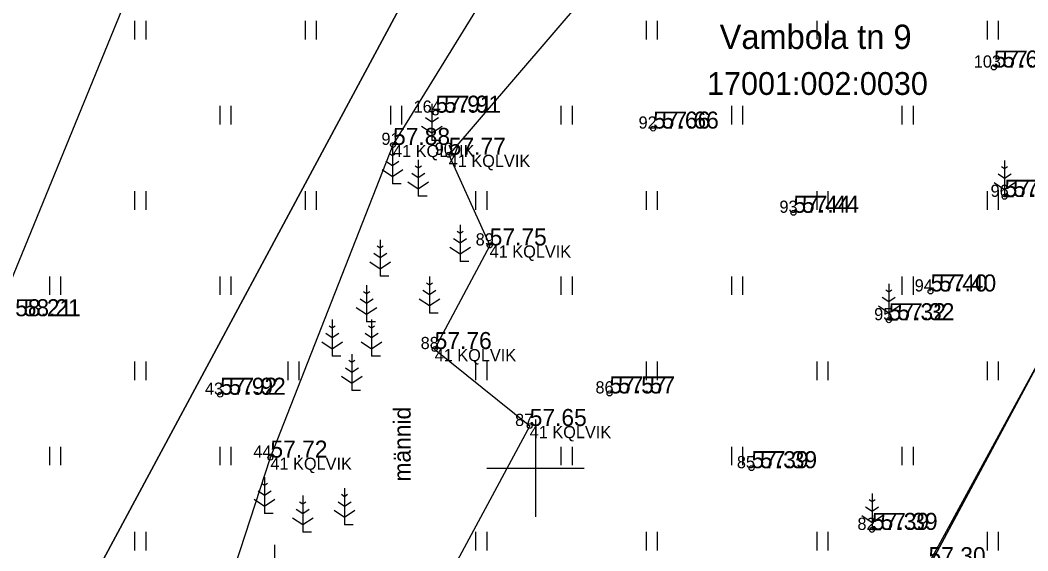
# Model space of a CAD drawing. Extents: x 640891 to 641083, y 6456526 to 6456669.
# Drawn here: x 640928.85 to 640970.21, y 6456596.6 to 6456618.41 of the extents above; entities that cross this region are included whole.
import ezdxf

# ---------------------------------------------------------------- set-up
doc = ezdxf.new("R2010")
doc.units = 0
for name, color, linetype in [('100koma2', 7, 'Continuous'), ('HALJASTUS', 7, 'Continuous'), ('KORGUS', 7, 'Continuous'), ('MOOTKORG', 7, 'Continuous'), ('MOOTMPUNKT', 7, 'Continuous'), ('MOOTNR', 7, 'Continuous'), ('MOOTPIIR', 7, 'Continuous'), ('PIIR', 7, 'Continuous'), ('PUU', 7, 'Continuous'), ('VORK', 7, 'Continuous')]:
    doc.layers.add(name, color=color, linetype=linetype)

msp = doc.modelspace()

# ---------------------------------------------------------------- linework, layer by layer
at = {"layer": 'HALJASTUS'}
for p, q in [((640933.545, 6456618.381), (640933.545, 6456617.619)), ((640934, 6456618.381), (640934, 6456617.619)), ((640940.545, 6456618.381), (640940.545, 6456617.619)), ((640941, 6456618.381), (640941, 6456617.619)), ((640954.545, 6456618.381), (640954.545, 6456617.619)), ((640955, 6456618.381), (640955, 6456617.619)), ((640961.545, 6456618.381), (640961.545, 6456617.619)), ((640962, 6456618.381), (640962, 6456617.619)), ((640968.545, 6456618.381), (640968.545, 6456617.619)), ((640969, 6456618.381), (640969, 6456617.619)), ((640937.045, 6456614.881), (640937.045, 6456614.119)), ((640937.5, 6456614.881), (640937.5, 6456614.119)), ((640944.045, 6456614.881), (640944.045, 6456614.119)), ((640944.5, 6456614.881), (640944.5, 6456614.119)), ((640951.045, 6456614.881), (640951.045, 6456614.119)), ((640951.5, 6456614.881), (640951.5, 6456614.119)), ((640958.045, 6456614.881), (640958.045, 6456614.119)), ((640958.5, 6456614.881), (640958.5, 6456614.119)), ((640965.045, 6456614.881), (640965.045, 6456614.119)), ((640965.5, 6456614.881), (640965.5, 6456614.119)), ((640933.545, 6456611.381), (640933.545, 6456610.619)), ((640934, 6456611.381), (640934, 6456610.619)), ((640940.545, 6456611.381), (640940.545, 6456610.619)), ((640941, 6456611.381), (640941, 6456610.619)), ((640947.545, 6456611.381), (640947.545, 6456610.619)), ((640948, 6456611.381), (640948, 6456610.619)), ((640954.545, 6456611.381), (640954.545, 6456610.619)), ((640955, 6456611.381), (640955, 6456610.619)), ((640961.545, 6456611.381), (640961.545, 6456610.619)), ((640962, 6456611.381), (640962, 6456610.619)), ((640968.545, 6456611.381), (640968.545, 6456610.619)), ((640969, 6456611.381), (640969, 6456610.619)), ((640930.045, 6456607.881), (640930.045, 6456607.119)), ((640930.5, 6456607.881), (640930.5, 6456607.119)), ((640937.045, 6456607.881), (640937.045, 6456607.119)), ((640937.5, 6456607.881), (640937.5, 6456607.119)), ((640951.045, 6456607.881), (640951.045, 6456607.119)), ((640951.5, 6456607.881), (640951.5, 6456607.119)), ((640958.045, 6456607.881), (640958.045, 6456607.119)), ((640958.5, 6456607.881), (640958.5, 6456607.119)), ((640965.045, 6456607.881), (640965.045, 6456607.119)), ((640965.5, 6456607.881), (640965.5, 6456607.119)), ((640933.545, 6456604.381), (640933.545, 6456603.619)), ((640934, 6456604.381), (640934, 6456603.619)), ((640939.828, 6456604.381), (640939.828, 6456603.619)), ((640940.283, 6456604.381), (640940.283, 6456603.619)), ((640947.545, 6456604.381), (640947.545, 6456603.619)), ((640948, 6456604.381), (640948, 6456603.619)), ((640954.545, 6456604.381), (640954.545, 6456603.619)), ((640955, 6456604.381), (640955, 6456603.619)), ((640961.545, 6456604.381), (640961.545, 6456603.619)), ((640962, 6456604.381), (640962, 6456603.619)), ((640968.545, 6456604.381), (640968.545, 6456603.619)), ((640969, 6456604.381), (640969, 6456603.619)), ((640930.045, 6456600.881), (640930.045, 6456600.119)), ((640930.5, 6456600.881), (640930.5, 6456600.119)), ((640937.045, 6456600.881), (640937.045, 6456600.119)), ((640937.5, 6456600.881), (640937.5, 6456600.119)), ((640951.045, 6456600.881), (640951.045, 6456600.119)), ((640951.5, 6456600.881), (640951.5, 6456600.119)), ((640958.045, 6456600.881), (640958.045, 6456600.119)), ((640958.5, 6456600.881), (640958.5, 6456600.119)), ((640965.045, 6456600.881), (640965.045, 6456600.119)), ((640965.5, 6456600.881), (640965.5, 6456600.119)), ((640933.545, 6456597.381), (640933.545, 6456596.619)), ((640934, 6456597.381), (640934, 6456596.619)), ((640947.545, 6456597.381), (640947.545, 6456596.619)), ((640948, 6456597.381), (640948, 6456596.619)), ((640954.545, 6456597.381), (640954.545, 6456596.619)), ((640955, 6456597.381), (640955, 6456596.619)), ((640961.545, 6456597.381), (640961.545, 6456596.619)), ((640962, 6456597.381), (640962, 6456596.619)), ((640968.545, 6456597.381), (640968.545, 6456596.619)), ((640969, 6456597.381), (640969, 6456596.619))]:
    msp.add_line(p, q, dxfattribs=at)
for points in [[(640940.859, 6456588.363), (640936.098, 6456589.959), (640937.267, 6456594.734), (640939.119, 6456600.434), (640944.153, 6456613.282), (640950.33, 6456623.315), (640954.177, 6456630.888), (640962.196, 6456639.436), (640963.998, 6456638.677), (640968.745, 6456632.01), (640966.503, 6456625.352), (640963.655, 6456626.075), (640962.794, 6456629.058), (640958.598, 6456629.914), (640954.818, 6456622.648), (640946.439, 6456612.875), (640948.12, 6456609.151), (640945.862, 6456604.895), (640949.763, 6456601.734), (640945.05, 6456592.964), (640940.483, 6456588.68)], [(640962.925, 6456576.62), (640957.383, 6456579.521), (640966.138, 6456596.056), (640972.417, 6456607.592), (640977.059, 6456616.501), (640985.041, 6456631.518)]]:
    msp.add_lwpolyline(points, dxfattribs=at)
at = {"layer": 'KORGUS'}
for centre in [(640968.818, 6456616.461), (640945.896, 6456614.606), (640954.833, 6456613.952), (640969.258, 6456611.148), (640960.591, 6456610.493), (640966.219, 6456607.261), (640964.504, 6456606.079), (640937.057, 6456603.018), (640953.038, 6456603.072), (640958.868, 6456600), (640963.817, 6456597.465)]:
    msp.add_circle(centre, 0.1, dxfattribs=at)
at = {"layer": 'MOOTMPUNKT'}
for centre in [(640968.818, 6456616.461), (640945.896, 6456614.606), (640954.833, 6456613.952), (640944.153, 6456613.282), (640946.439, 6456612.875), (640969.258, 6456611.148), (640960.591, 6456610.493), (640948.12, 6456609.151), (640966.219, 6456607.261), (640964.504, 6456606.079), (640945.862, 6456604.895), (640937.057, 6456603.018), (640953.038, 6456603.072), (640949.763, 6456601.734), (640939.119, 6456600.434), (640958.868, 6456600), (640963.817, 6456597.465)]:
    msp.add_circle(centre, 0.1, dxfattribs=at)
at = {"layer": 'MOOTPIIR'}
msp.add_lwpolyline([(640976.662, 6456538.007), (640959.29, 6456546.142), (640961.328, 6456555.553), (640965.053, 6456562.959), (640957.364, 6456564.816), (640935.712, 6456572.952), (640933.007, 6456573.069), (640928.881, 6456566.092), (640925.582, 6456561.827), (640921.958, 6456562.765), (640911.417, 6456572.885), (640912.029, 6456574.013), (640921.076, 6456588.216), (640912.945, 6456593.7), (640910.627, 6456595.318), (640915.929, 6456603.505), (640924.706, 6456598.502), (640938.233, 6456631.58)], dxfattribs=at)
at = {"layer": 'PIIR'}
for points in [[(640930.79, 6456593.51), (640904.36, 6456607.7), (640935.64, 6456665.95), (640960.76, 6456649.34)], [(640957.22, 6456579.32), (640930.79, 6456593.51), (640960.76, 6456649.34), (640985.89, 6456632.73)], [(640983.63, 6456565.13), (640957.22, 6456579.32), (640985.89, 6456632.73), (641000.58, 6456623), (641011.01, 6456616.1)]]:
    msp.add_lwpolyline(points, close=True, dxfattribs=at)
at = {"layer": 'PUU'}
for p, q in [((640945.749, 6456614.969), (640945.749, 6456613.469)), ((640945.749, 6456614.219), (640945.483, 6456614.397)), ((640945.749, 6456614.619), (640945.625, 6456614.702)), ((640945.874, 6456614.702), (640945.749, 6456614.619)), ((640946.016, 6456614.397), (640945.749, 6456614.219)), ((640945.325, 6456614.058), (640945.749, 6456613.775)), ((640945.749, 6456613.775), (640946.173, 6456614.058)), ((640944.131, 6456613.178), (640944.131, 6456611.678)), ((640946.109, 6456613.469), (640945.749, 6456613.469)), ((640944.131, 6456612.828), (640944.006, 6456612.911)), ((640944.255, 6456612.911), (640944.131, 6456612.828)), ((640944.131, 6456612.428), (640943.864, 6456612.606)), ((640944.397, 6456612.606), (640944.131, 6456612.428)), ((640945.191, 6456612.323), (640945.067, 6456612.406)), ((640945.191, 6456612.673), (640945.191, 6456611.173)), ((640945.316, 6456612.406), (640945.191, 6456612.323)), ((640969.258, 6456612.298), (640969.134, 6456612.381)), ((640969.258, 6456612.648), (640969.258, 6456611.148)), ((640969.383, 6456612.381), (640969.258, 6456612.298)), ((640943.706, 6456612.268), (640944.131, 6456611.985)), ((640944.131, 6456611.985), (640944.555, 6456612.268)), ((640945.191, 6456611.923), (640944.924, 6456612.101)), ((640945.458, 6456612.101), (640945.191, 6456611.923)), ((640969.258, 6456611.898), (640968.992, 6456612.076)), ((640969.525, 6456612.076), (640969.258, 6456611.898)), ((640944.491, 6456611.678), (640944.131, 6456611.678)), ((640944.767, 6456611.762), (640945.191, 6456611.479)), ((640945.191, 6456611.479), (640945.615, 6456611.762)), ((640968.834, 6456611.737), (640969.258, 6456611.454)), ((640969.258, 6456611.454), (640969.683, 6456611.737)), ((640945.551, 6456611.173), (640945.191, 6456611.173)), ((640969.618, 6456611.148), (640969.258, 6456611.148)), ((640946.908, 6456609.995), (640946.908, 6456608.495)), ((640946.908, 6456609.245), (640946.642, 6456609.422)), ((640946.908, 6456609.645), (640946.784, 6456609.728)), ((640947.033, 6456609.728), (640946.908, 6456609.645)), ((640947.175, 6456609.422), (640946.908, 6456609.245)), ((640943.626, 6456609.038), (640943.501, 6456609.121)), ((640943.626, 6456609.388), (640943.626, 6456607.888)), ((640943.75, 6456609.121), (640943.626, 6456609.038)), ((640946.484, 6456609.084), (640946.908, 6456608.801)), ((640946.908, 6456608.801), (640947.332, 6456609.084)), ((640943.626, 6456608.638), (640943.359, 6456608.816)), ((640943.892, 6456608.816), (640943.626, 6456608.638)), ((640943.201, 6456608.478), (640943.626, 6456608.195)), ((640943.626, 6456608.195), (640944.05, 6456608.478)), ((640947.268, 6456608.495), (640946.908, 6456608.495)), ((640943.986, 6456607.888), (640943.626, 6456607.888)), ((640945.646, 6456607.872), (640945.646, 6456606.372)), ((640943.07, 6456607.518), (640943.07, 6456606.018)), ((640945.646, 6456607.522), (640945.521, 6456607.605)), ((640945.77, 6456607.605), (640945.646, 6456607.522)), ((640964.504, 6456607.579), (640964.504, 6456606.079)), ((640943.07, 6456606.768), (640942.803, 6456606.946)), ((640943.07, 6456607.168), (640942.946, 6456607.251)), ((640943.194, 6456607.251), (640943.07, 6456607.168)), ((640943.337, 6456606.946), (640943.07, 6456606.768)), ((640945.221, 6456606.961), (640945.646, 6456606.679)), ((640945.646, 6456607.122), (640945.379, 6456607.3)), ((640945.912, 6456607.3), (640945.646, 6456607.122)), ((640945.646, 6456606.679), (640946.07, 6456606.961)), ((640964.504, 6456606.829), (640964.237, 6456607.007)), ((640964.504, 6456607.229), (640964.379, 6456607.312)), ((640964.628, 6456607.312), (640964.504, 6456607.229)), ((640964.77, 6456607.007), (640964.504, 6456606.829)), ((640942.646, 6456606.608), (640943.07, 6456606.325)), ((640943.07, 6456606.325), (640943.494, 6456606.608)), ((640964.08, 6456606.669), (640964.504, 6456606.386)), ((640964.504, 6456606.386), (640964.928, 6456606.669)), ((640941.656, 6456606.103), (640941.656, 6456604.603)), ((640943.272, 6456606.103), (640943.272, 6456604.603)), ((640946.006, 6456606.372), (640945.646, 6456606.372)), ((640941.656, 6456605.753), (640941.532, 6456605.836)), ((640941.78, 6456605.836), (640941.656, 6456605.753)), ((640943.43, 6456606.018), (640943.07, 6456606.018)), ((640943.272, 6456605.753), (640943.148, 6456605.836)), ((640943.396, 6456605.836), (640943.272, 6456605.753)), ((640964.864, 6456606.079), (640964.504, 6456606.079)), ((640941.656, 6456605.353), (640941.389, 6456605.531)), ((640941.923, 6456605.531), (640941.656, 6456605.353)), ((640943.272, 6456605.353), (640943.005, 6456605.531)), ((640943.539, 6456605.531), (640943.272, 6456605.353)), ((640941.232, 6456605.193), (640941.656, 6456604.91)), ((640941.656, 6456604.91), (640942.08, 6456605.193)), ((640942.848, 6456605.193), (640943.272, 6456604.91)), ((640943.272, 6456604.91), (640943.696, 6456605.193)), ((640942.016, 6456604.603), (640941.656, 6456604.603)), ((640942.464, 6456604.688), (640942.464, 6456603.188)), ((640943.632, 6456604.603), (640943.272, 6456604.603)), ((640942.464, 6456603.938), (640942.197, 6456604.116)), ((640942.464, 6456604.338), (640942.34, 6456604.421)), ((640942.588, 6456604.421), (640942.464, 6456604.338)), ((640942.731, 6456604.116), (640942.464, 6456603.938)), ((640942.04, 6456603.778), (640942.464, 6456603.495)), ((640942.464, 6456603.495), (640942.888, 6456603.778)), ((640942.824, 6456603.188), (640942.464, 6456603.188)), ((640938.878, 6456599.635), (640938.878, 6456598.135)), ((640938.878, 6456598.885), (640938.612, 6456599.063)), ((640938.878, 6456599.285), (640938.754, 6456599.368)), ((640939.003, 6456599.368), (640938.878, 6456599.285)), ((640939.145, 6456599.063), (640938.878, 6456598.885)), ((640942.161, 6456599.18), (640942.161, 6456597.68)), ((640938.454, 6456598.724), (640938.878, 6456598.442)), ((640938.878, 6456598.442), (640939.303, 6456598.724)), ((640940.444, 6456598.877), (640940.444, 6456597.377)), ((640942.161, 6456598.83), (640942.037, 6456598.913)), ((640942.285, 6456598.913), (640942.161, 6456598.83)), ((640963.817, 6456598.615), (640963.693, 6456598.698)), ((640963.817, 6456598.965), (640963.817, 6456597.465)), ((640963.942, 6456598.698), (640963.817, 6456598.615)), ((640940.444, 6456598.127), (640940.177, 6456598.305)), ((640940.444, 6456598.527), (640940.32, 6456598.61)), ((640940.568, 6456598.61), (640940.444, 6456598.527)), ((640940.711, 6456598.305), (640940.444, 6456598.127)), ((640941.737, 6456598.27), (640942.161, 6456597.987)), ((640942.161, 6456598.43), (640941.894, 6456598.608)), ((640942.428, 6456598.608), (640942.161, 6456598.43)), ((640942.161, 6456597.987), (640942.585, 6456598.27)), ((640963.817, 6456598.215), (640963.551, 6456598.393)), ((640964.084, 6456598.393), (640963.817, 6456598.215)), ((640939.238, 6456598.135), (640938.878, 6456598.135)), ((640940.02, 6456597.966), (640940.444, 6456597.684)), ((640940.444, 6456597.684), (640940.868, 6456597.966)), ((640963.393, 6456598.055), (640963.817, 6456597.772)), ((640963.817, 6456597.772), (640964.242, 6456598.055)), ((640942.521, 6456597.68), (640942.161, 6456597.68)), ((640964.177, 6456597.465), (640963.817, 6456597.465)), ((640940.804, 6456597.377), (640940.444, 6456597.377)), ((640939.282, 6456596.856), (640939.282, 6456595.356))]:
    msp.add_line(p, q, dxfattribs=at)
at = {"layer": 'VORK'}
for p, q in [((640950, 6456602), (640950, 6456598)), ((640948, 6456600), (640952, 6456600))]:
    msp.add_line(p, q, dxfattribs=at)

# ---------------------------------------------------------------- texts
at = {"layer": '100koma2'}
for p in [(640944.153, 6456612.782), (640946.439, 6456612.375), (640948.12, 6456608.651), (640945.862, 6456604.395), (640949.763, 6456601.234), (640939.119, 6456599.934)]:
    msp.add_text('41 KQLVIK', height=0.5, dxfattribs=at).set_placement(p)
at = {"layer": 'HALJASTUS'}
msp.add_text('männid', height=0.7, rotation=90, dxfattribs=at).set_placement((640944.876, 6456599.451))
at = {"layer": 'KORGUS'}
for s, p in [('57.68', (640969.168, 6456616.461)), ('57.91', (640946.246, 6456614.606)), ('57.66', (640955.183, 6456613.952)), ('57.53', (640969.608, 6456611.148)), ('57.44', (640960.941, 6456610.493)), ('57.40', (640966.569, 6456607.261)), ('58.21', (640928.992, 6456606.243)), ('57.32', (640964.854, 6456606.079)), ('57.92', (640937.407, 6456603.018)), ('57.57', (640953.388, 6456603.072)), ('57.39', (640959.218, 6456600)), ('57.39', (640964.167, 6456597.465))]:
    msp.add_text(s, height=0.7, dxfattribs=at).set_placement(p)
at = {"layer": 'MOOTKORG'}
for s, p in [('57.68', (640968.818, 6456616.461)), ('57.91', (640945.896, 6456614.606)), ('57.66', (640954.833, 6456613.952)), ('57.88', (640944.153, 6456613.282)), ('57.77', (640946.439, 6456612.875)), ('57.53', (640969.258, 6456611.148)), ('57.44', (640960.591, 6456610.493)), ('57.75', (640948.12, 6456609.151)), ('57.40', (640966.219, 6456607.261)), ('58.21', (640928.642, 6456606.243)), ('57.32', (640964.504, 6456606.079)), ('57.76', (640945.862, 6456604.895)), ('57.92', (640937.057, 6456603.018)), ('57.57', (640953.038, 6456603.072)), ('57.65', (640949.763, 6456601.734)), ('57.72', (640939.119, 6456600.434)), ('57.39', (640958.868, 6456600)), ('57.39', (640963.817, 6456597.465)), ('57.30', (640966.138, 6456596.056))]:
    msp.add_text(s, height=0.7, dxfattribs=at).set_placement(p)
at = {"layer": 'MOOTNR'}
for s, p in [('103', (640967.993, 6456616.461)), ('164', (640944.997, 6456614.606)), ('92', (640954.233, 6456613.952)), ('91', (640943.678, 6456613.282)), ('90', (640945.864, 6456612.875)), ('96', (640968.683, 6456611.148)), ('93', (640960.016, 6456610.493)), ('89', (640947.545, 6456609.151)), ('94', (640965.569, 6456607.261)), ('95', (640963.904, 6456606.079)), ('88', (640945.287, 6456604.895)), ('43', (640936.432, 6456603.018)), ('86', (640952.463, 6456603.072)), ('87', (640949.163, 6456601.734)), ('44', (640938.419, 6456600.434)), ('85', (640958.268, 6456600)), ('82', (640963.217, 6456597.465))]:
    msp.add_text(s, height=0.5, dxfattribs=at).set_placement(p)
at = {"layer": 'PIIR'}
for s, height, p in [('Vambola tn 9', 1.00002, (640957.561, 6456617.224)), ('17001:002:0030', 0.9375, (640957.044, 6456615.336))]:
    msp.add_text(s, height=height, dxfattribs=at).set_placement(p)

doc.saveas('drawing.dxf')
